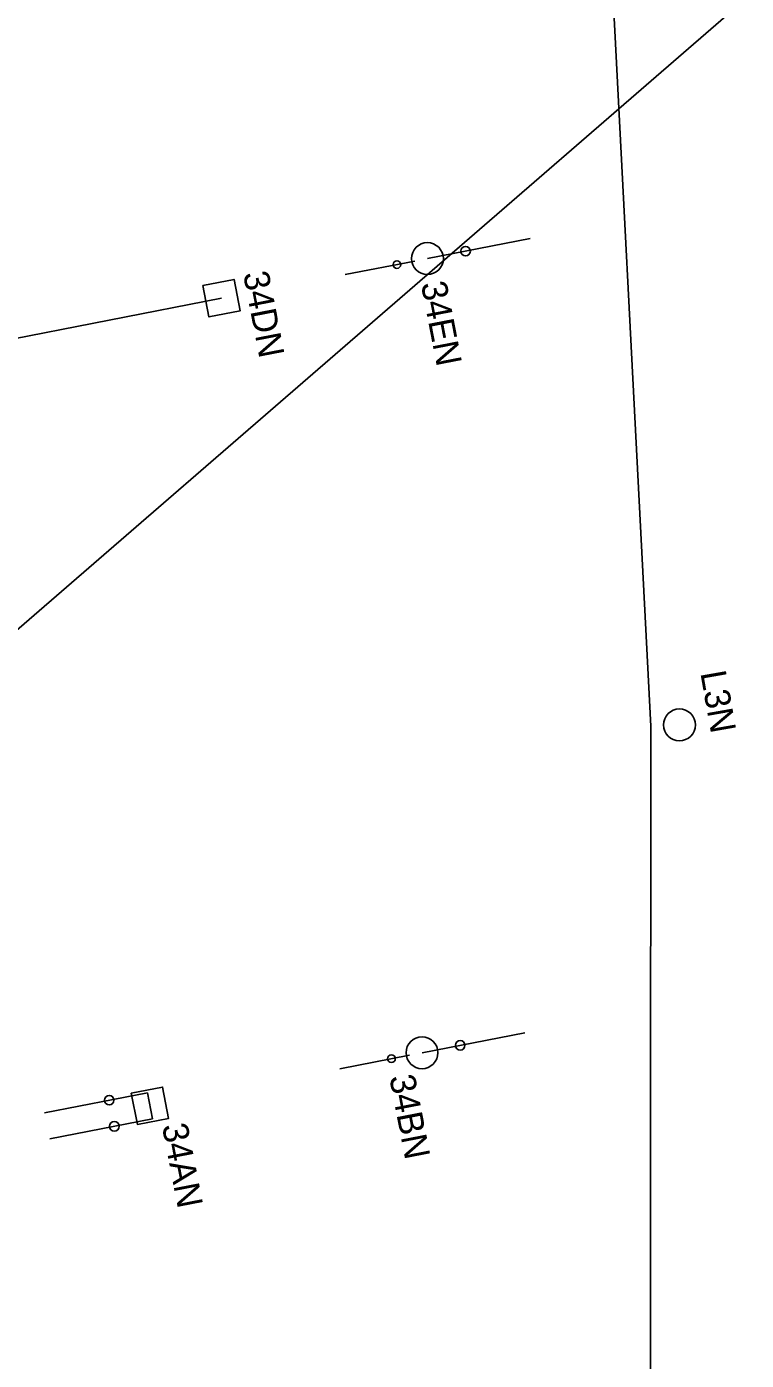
# Model space of a CAD drawing. Extents: x -545258 to -544992, y -1122311 to -1121664.
# Drawn here: x -545136.9 to -545101.7, y -1122054.6 to -1121989.4 of the extents above; entities that cross this region are included whole.
import ezdxf

# ---------------------------------------------------------------- set-up
doc = ezdxf.new("R2010")
doc.units = 0
for name, color, linetype in [('SO 18-01-01_3', 7, 'Continuous'), ('SO 18-01-01_4', 7, 'Continuous'), ('SOPS', 7, 'Continuous')]:
    doc.layers.add(name, color=color, linetype=linetype)

msp = doc.modelspace()

# ---------------------------------------------------------------- linework, layer by layer
at = {"layer": 'SO 18-01-01_3'}
for p, q in [((-545117.295, -1122000.728), (-545112.266, -1121999.747)), ((-545117.907, -1122000.846), (-545121.317, -1122001.511)), ((-545127.367, -1122002.664), (-545150.694, -1122007.211)), ((-545117.558, -1122039.557), (-545112.53, -1122038.577)), ((-545118.171, -1122039.675), (-545121.581, -1122040.34)), ((-545130.993, -1122041.512), (-545136.021, -1122042.496)), ((-545130.744, -1122042.788), (-545130.993, -1122041.512)), ((-545130.744, -1122042.788), (-545135.772, -1122043.772))]:
    msp.add_line(p, q, dxfattribs=at)
for points in [[(-545128.281, -1122002.048), (-545127.983, -1122003.579), (-545126.452, -1122003.281), (-545126.75, -1122001.749)], [(-545131.784, -1122041.534), (-545131.485, -1122043.065), (-545129.954, -1122042.767), (-545130.253, -1122041.236)]]:
    msp.add_lwpolyline(points, close=True, dxfattribs=at)
for centre, radius in [((-545117.295, -1122000.727), 0.78), ((-545115.427, -1122000.364), 0.234), ((-545118.789, -1122001.018), 0.187), ((-545104.964, -1122023.528), 0.78), ((-545117.558, -1122039.556), 0.78), ((-545115.69, -1122039.193), 0.234), ((-545119.052, -1122039.847), 0.187), ((-545132.861, -1122041.878), 0.234), ((-545132.612, -1122043.153), 0.234)]:
    msp.add_circle(centre, radius, dxfattribs=at)
at = {"layer": 'SO 18-01-01_4'}
msp.add_lwpolyline([(-545102.793, -1122250.491), (-545106.116, -1122208.618), (-545109.928, -1122137.596), (-545106.412, -1122088.188), (-545106.367, -1122023.596), (-545108.703, -1121978.559), (-545127.424, -1121916.593), (-545139.015, -1121857.213), (-545147.82, -1121812.064), (-545159.299, -1121753.172), (-545170.035, -1121688.35), (-545174.127, -1121676.058)], dxfattribs=at)
msp.add_circle((-545104.964, -1122023.528), 0.78, dxfattribs=at)
at = {"layer": 'SOPS'}
msp.add_line((-545100.371, -1121986.851), (-545175.795, -1122052.141), dxfattribs=at)

# ---------------------------------------------------------------- texts
at = {"layer": 'SO 18-01-01_3'}
for s, p in [('34DN', (-545126.315, -1122001.46)), ('34EN', (-545117.616, -1122001.956)), ('34BN', (-545119.164, -1122040.742)), ('34AN', (-545130.285, -1122043.123))]:
    msp.add_text(s, height=1.25, rotation=280.95707, dxfattribs=at).set_placement(p)
at = {"layer": 'SO 18-01-01_4'}
msp.add_text('L3N', height=1.25, rotation=280.00289, dxfattribs=at).set_placement((-545103.944, -1122020.981))

doc.saveas('drawing.dxf')
